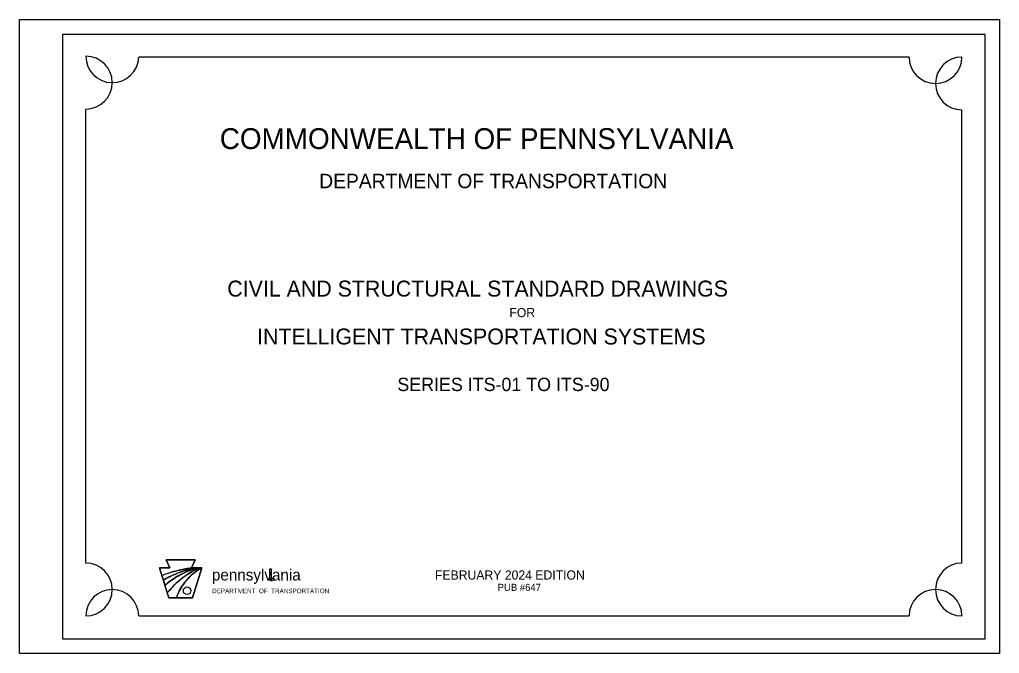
# Model space of a CAD drawing. Extents: x 1299166 to 1299200, y 239631.7 to 239653.7.
import ezdxf

# ---------------------------------------------------------------- set-up
doc = ezdxf.new("R2010")
doc.units = 0
for name, color, linetype in [('1', 7, 'Continuous'), ('2', 7, 'Continuous'), ('Default', 7, 'Continuous'), ('GS_plotshape_p', 7, 'Continuous'), ('Level 1', 7, 'Continuous'), ('Level 2', 7, 'Continuous')]:
    doc.layers.add(name, color=color, linetype=linetype)

msp = doc.modelspace()

# ---------------------------------------------------------------- linework, layer by layer
at = {"layer": '1'}
for p, q in [((1299171.222, 239634.648), (1299171.095, 239634.924)), ((1299171.095, 239634.924), (1299172.107, 239634.924)), ((1299172.107, 239634.924), (1299171.979, 239634.648)), ((1299171.188, 239633.607), (1299170.869, 239634.648)), ((1299170.869, 239634.648), (1299171.222, 239634.648)), ((1299171.979, 239634.648), (1299172.332, 239634.648)), ((1299172.332, 239634.648), (1299172.013, 239633.607)), ((1299172.013, 239633.607), (1299171.188, 239633.607))]:
    msp.add_line(p, q, dxfattribs=at)
for points in [[(1299171.979, 239634.648), (1299172.107, 239634.924), (1299171.095, 239634.924), (1299171.222, 239634.648), (1299170.869, 239634.648), (1299170.951, 239634.381), (1299171.086, 239634.432), (1299171.209, 239634.472), (1299171.311, 239634.503), (1299171.419, 239634.532), (1299171.494, 239634.551), (1299171.556, 239634.567), (1299171.665, 239634.592), (1299171.828, 239634.623), (1299171.923, 239634.639)], [(1299171.979, 239634.648), (1299171.909, 239634.637), (1299171.827, 239634.622), (1299171.751, 239634.608), (1299171.666, 239634.591), (1299171.551, 239634.565), (1299171.425, 239634.533), (1299171.311, 239634.502), (1299171.187, 239634.464), (1299171.121, 239634.443), (1299171.077, 239634.428), (1299170.989, 239634.395), (1299170.951, 239634.381), (1299171.001, 239634.219), (1299171.084, 239634.267), (1299171.171, 239634.314), (1299171.192, 239634.325), (1299171.246, 239634.35), (1299171.331, 239634.391), (1299171.418, 239634.428), (1299171.512, 239634.467), (1299171.586, 239634.495), (1299171.677, 239634.527), (1299171.765, 239634.555), (1299171.865, 239634.584), (1299171.949, 239634.609), (1299172.039, 239634.632), (1299172.1, 239634.648)], [(1299172.1, 239634.649), (1299171.938, 239634.606), (1299171.716, 239634.54), (1299171.531, 239634.475), (1299171.365, 239634.407), (1299171.183, 239634.32), (1299171.04, 239634.242), (1299171.001, 239634.219), (1299171.056, 239634.04), (1299171.138, 239634.112), (1299171.199, 239634.158), (1299171.274, 239634.212), (1299171.284, 239634.219), (1299171.338, 239634.256), (1299171.412, 239634.303), (1299171.473, 239634.341), (1299171.5, 239634.356), (1299171.598, 239634.412), (1299171.61, 239634.418), (1299171.669, 239634.45), (1299171.701, 239634.466), (1299171.733, 239634.482), (1299171.821, 239634.521), (1299171.882, 239634.545), (1299171.972, 239634.581), (1299172.082, 239634.618), (1299172.172, 239634.648)], [(1299172.172, 239634.648), (1299172.075, 239634.616), (1299171.973, 239634.581), (1299171.895, 239634.551), (1299171.796, 239634.511), (1299171.696, 239634.465), (1299171.585, 239634.405), (1299171.555, 239634.388), (1299171.473, 239634.341), (1299171.374, 239634.279), (1299171.283, 239634.219), (1299171.199, 239634.159), (1299171.186, 239634.148), (1299171.141, 239634.114), (1299171.117, 239634.093), (1299171.099, 239634.078), (1299171.056, 239634.04), (1299171.137, 239633.774), (1299171.238, 239633.891), (1299171.323, 239633.984), (1299171.4, 239634.063), (1299171.493, 239634.155), (1299171.594, 239634.241), (1299171.666, 239634.296), (1299171.755, 239634.366), (1299171.835, 239634.42), (1299171.925, 239634.477), (1299172.014, 239634.531), (1299172.079, 239634.57), (1299172.174, 239634.619), (1299172.24, 239634.648)], [(1299172.24, 239634.648), (1299172.166, 239634.616), (1299172.055, 239634.556), (1299171.918, 239634.472), (1299171.764, 239634.371), (1299171.631, 239634.269), (1299171.558, 239634.211), (1299171.438, 239634.101), (1299171.364, 239634.027), (1299171.267, 239633.924), (1299171.203, 239633.851), (1299171.137, 239633.774), (1299171.188, 239633.607), (1299171.453, 239633.607), (1299171.47, 239633.654), (1299171.51, 239633.749), (1299171.522, 239633.779), (1299171.532, 239633.802), (1299171.554, 239633.843), (1299171.61, 239633.947), (1299171.66, 239634.03), (1299171.73, 239634.127), (1299171.787, 239634.197), (1299171.81, 239634.223), (1299171.861, 239634.28), (1299171.895, 239634.316), (1299171.978, 239634.399), (1299172.056, 239634.463), (1299172.121, 239634.515), (1299172.2, 239634.569), (1299172.281, 239634.618), (1299172.332, 239634.648)], [(1299172.332, 239634.648), (1299172.282, 239634.619), (1299172.206, 239634.573), (1299172.123, 239634.517), (1299172.045, 239634.454), (1299171.979, 239634.399), (1299171.933, 239634.355), (1299171.855, 239634.274), (1299171.779, 239634.189), (1299171.73, 239634.128), (1299171.717, 239634.109), (1299171.661, 239634.031), (1299171.613, 239633.952), (1299171.578, 239633.889), (1299171.53, 239633.798), (1299171.481, 239633.68), (1299171.453, 239633.607), (1299172.013, 239633.607)]]:
    msp.add_lwpolyline(points, close=True, dxfattribs=at)
msp.add_circle((1299171.825, 239633.853), 0.131, dxfattribs=at)
at = {"layer": '2'}
for p, q in [((1299174.745, 239634.206), (1299174.746, 239634.273)), ((1299174.747, 239634.28), (1299174.759, 239634.27)), ((1299174.747, 239634.275), (1299174.755, 239634.27)), ((1299174.815, 239634.295), (1299174.85, 239634.239))]:
    msp.add_line(p, q, dxfattribs=at)
msp.add_lwpolyline([(1299174.688, 239634.601), (1299174.688, 239634.244), (1299174.697, 239634.22), (1299174.724, 239634.204), (1299174.749, 239634.204), (1299174.748, 239634.601)], close=True, dxfattribs=at)
for major_axis in [(-0.139, 0), (-0.0547, 0)]:
    msp.add_ellipse((1299174.75, 239634.314), major_axis=major_axis, ratio=0.782967, start_param=1.534978, end_param=2.37838, dxfattribs=at)
at = {"layer": 'Default'}
msp.add_line((1299168.311, 239634.809), (1299168.311, 239650.571), dxfattribs=at)
msp.add_lwpolyline([(1299170.145, 239632.975), (1299196.878, 239632.975)], dxfattribs=at)
at = {"layer": 'GS_plotshape_p'}
msp.add_lwpolyline([(1299166.011, 239653.675), (1299200.011, 239653.675), (1299200.011, 239631.675), (1299166.011, 239631.675)], close=True, dxfattribs=at)
at = {"layer": 'Level 1'}
msp.add_lwpolyline([(1299199.511, 239632.175), (1299167.511, 239632.175), (1299167.511, 239653.175), (1299199.511, 239653.175)], close=True, dxfattribs=at)
at = {"layer": 'Level 2'}
for points in [[(1299196.878, 239652.375), (1299170.144, 239652.375)], [(1299198.711, 239634.809), (1299198.711, 239650.542)]]:
    msp.add_lwpolyline(points, dxfattribs=at)
for centre, start, end in [((1299169.228, 239652.404), 180, 358.2117), ((1299168.311, 239651.487), 270, 90), ((1299197.795, 239652.375), 180, 0), ((1299198.711, 239651.459), 90, 270), ((1299168.311, 239633.892), 270, 90), ((1299198.711, 239633.892), 90, 270), ((1299169.228, 239632.975), 0, 180), ((1299197.795, 239632.975), 0, 180)]:
    msp.add_arc(centre, 0.917, start, end, dxfattribs=at)

# ---------------------------------------------------------------- texts
at = {"layer": '2'}
for s, height, p in [('pennsylvania', 0.39486, (1299172.684, 239634.206)), ('DEPARTMENT  OF  TRANSPORTATION', 0.15794, (1299172.694, 239633.766))]:
    msp.add_text(s, height=height, dxfattribs=at).set_placement(p)
at = {"layer": 'Level 1'}
for s, height, p in [('COMMONWEALTH OF PENNSYLVANIA', 0.72275, (1299172.958, 239649.182)), ('DEPARTMENT OF TRANSPORTATION', 0.5, (1299176.409, 239647.823)), ('CIVIL AND STRUCTURAL STANDARD DRAWINGS', 0.55415, (1299173.218, 239644.061)), ('FOR', 0.3167, (1299183.007, 239643.348)), ('INTELLIGENT TRANSPORTATION SYSTEMS', 0.55415, (1299174.252, 239642.398)), ('SERIES ITS-01 TO ITS-90', 0.46298, (1299179.12, 239640.781)), ('FEBRUARY 2024 EDITION', 0.31665, (1299180.425, 239634.238)), ('PUB #647', 0.2463, (1299182.601, 239633.845))]:
    msp.add_text(s, height=height, dxfattribs=at).set_placement(p)

doc.saveas('drawing.dxf')
